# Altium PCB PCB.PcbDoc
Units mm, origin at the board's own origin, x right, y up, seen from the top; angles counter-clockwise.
Board outline 41 x 25.36 mm, 2 copper layers (TOP, BOTTOM), stack 1.586 mm thick; 28 components, 6 nets, 57 pads, 22 vias.
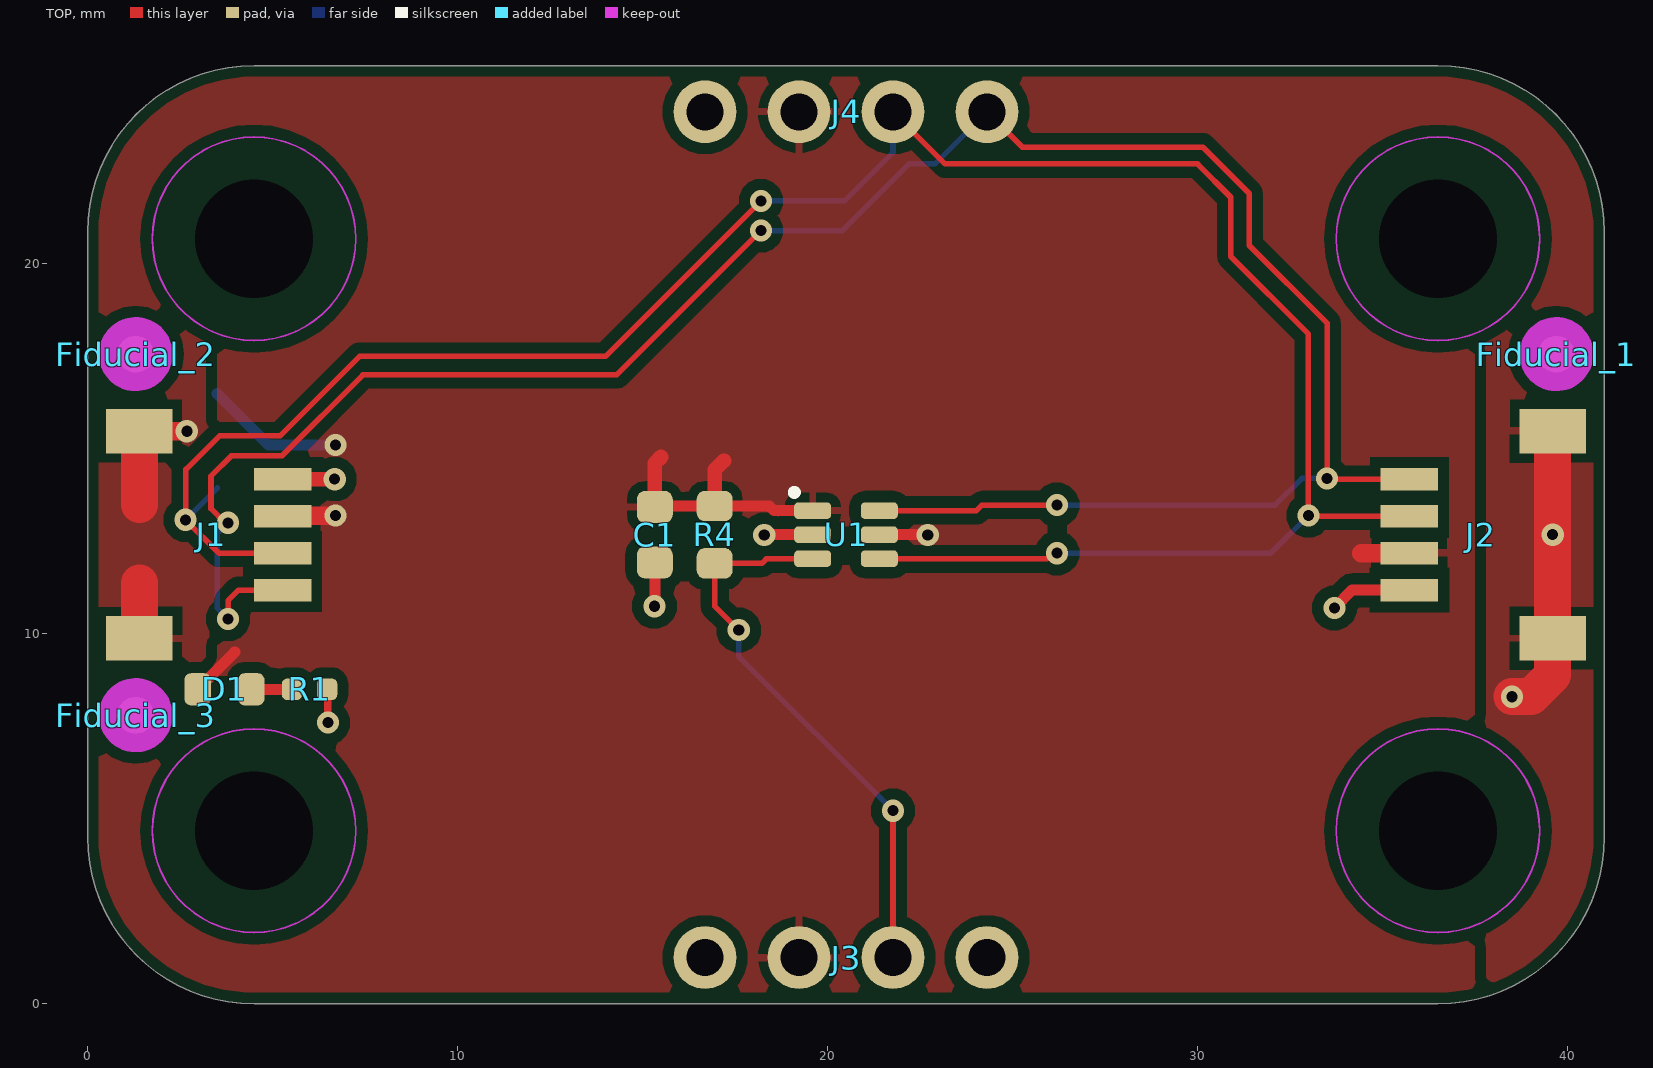
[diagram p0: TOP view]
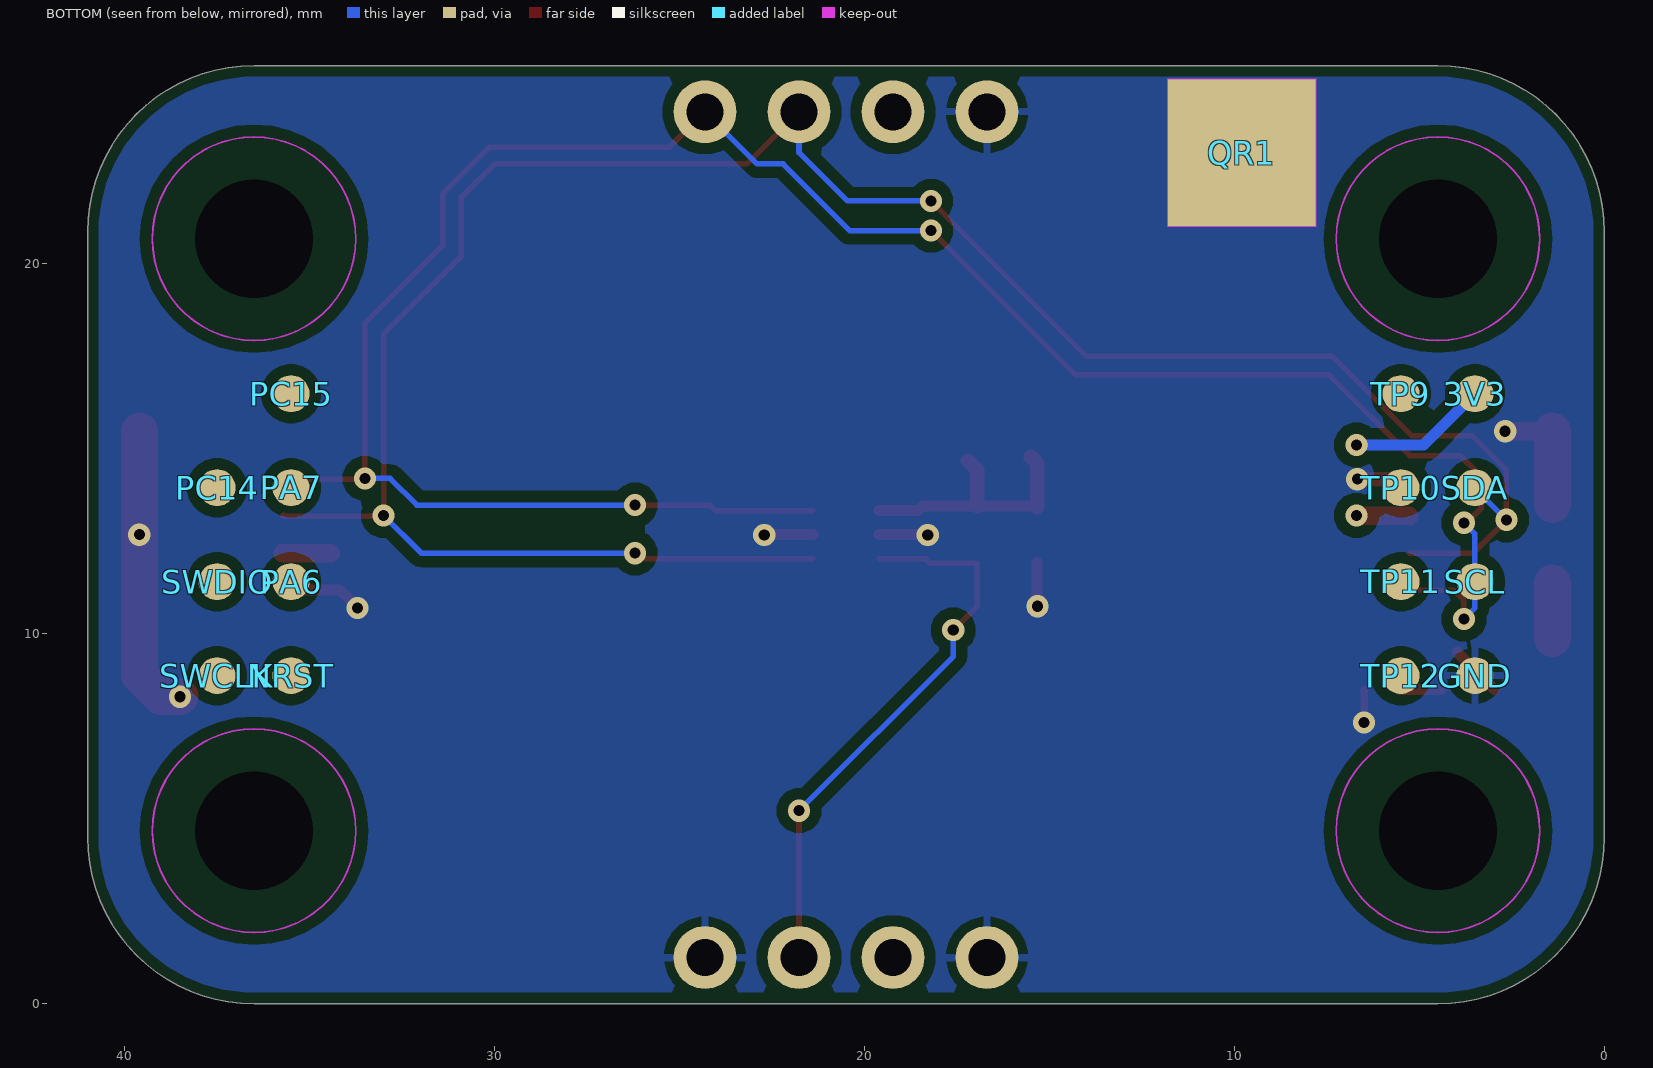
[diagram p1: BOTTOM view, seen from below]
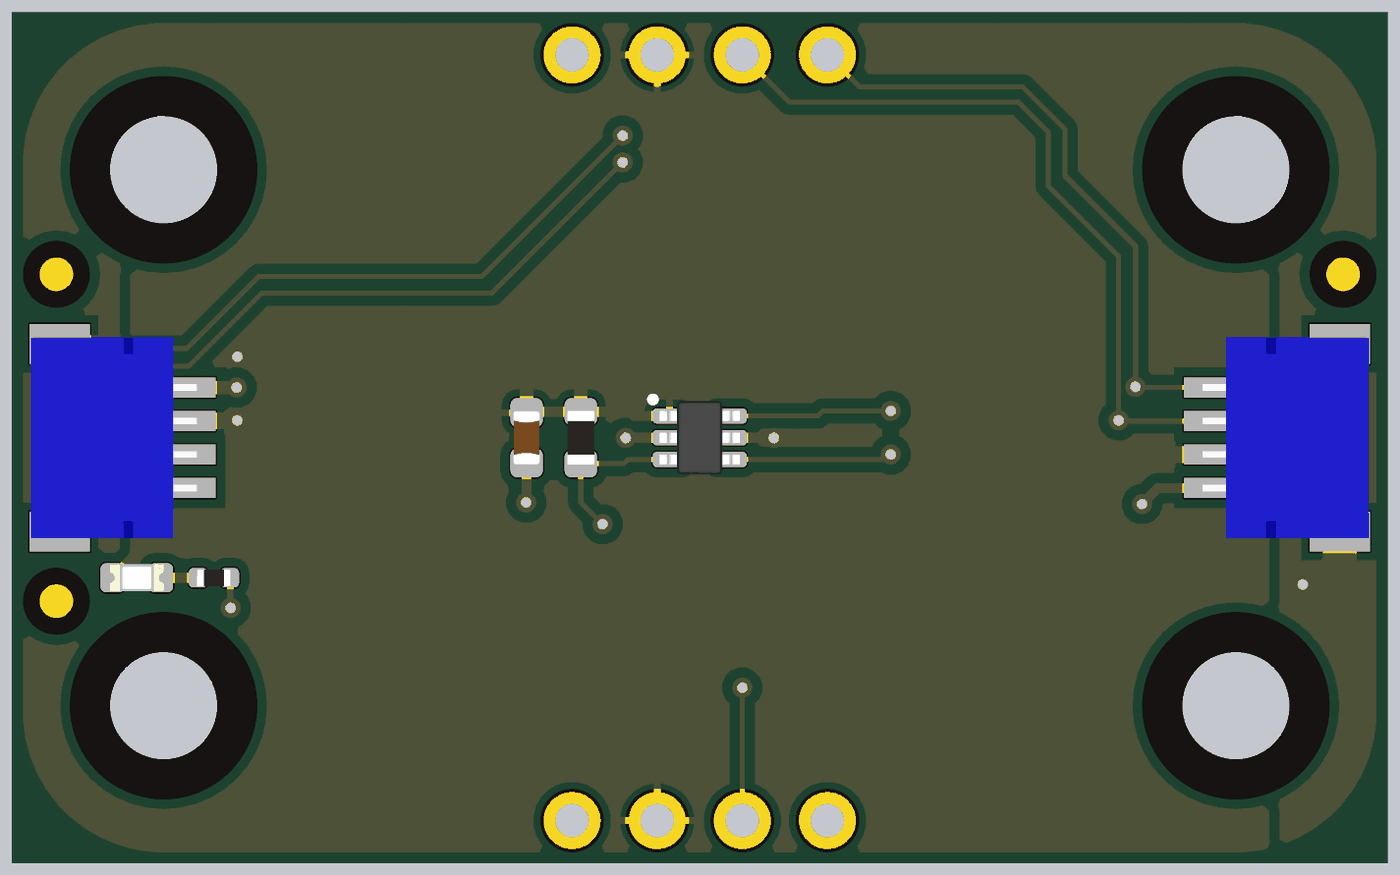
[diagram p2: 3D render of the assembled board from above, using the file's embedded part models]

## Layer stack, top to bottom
Top Solder: solder mask 0.01, Solder Resist, Dk 3.5
TOP: signal copper 0.018
Dielectric: core 1.55, FR-4, Dk 4.8
BOTTOM: signal copper 0.018
Bottom Solder: solder mask 0.01, Solder Resist, Dk 3.5

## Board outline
0,4.5 ccw(c4.5,4.5) 4.5,0 36.5,0 ccw(c36.5,4.5) 41,4.5 41,20.86 ccw(c36.5,20.86) 36.5,25.36 4.5,25.36 ccw(c4.5,20.86) 0,20.86

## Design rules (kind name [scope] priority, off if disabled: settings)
BoardOutlineClearance Mousebites [(ObjectKind = 'Pad') And (Name = 'Free-MOUSEBITE')] p1: gap=0 ignorepadtopadclearanceinfootprint=FALSE
BoardOutlineClearance Silks [(OnLayer('Top Overlay') OR OnLayer('Bottom Overlay'))] p2: gap=0 ignorepadtopadclearanceinfootprint=FALSE
BoardOutlineClearance [All] p3: gap=0.3 ignorepadtopadclearanceinfootprint=FALSE
Clearance COPPER_0.3mm [All] p1: gap=0.127 ignorepadtopadclearanceinfootprint=FALSE except(0.3: Arc-Fill Arc-Poly Arc-Region Track-Fill Track-Poly Track-Region SMDPad-Fill SMDPad-Poly SMDPad-Region THPad-Fill THPad-Poly THPad-Region Via-Fill Via-Poly Via-Region Fill-Fill Fill-Poly Fill-Region Poly-Poly Poly-Region Region-Region)
Clearance "Generic clearance 0.15mm" [All] p2: gap=0.15 ignorepadtopadclearanceinfootprint=FALSE
ComponentClearance [All] p1: gap=0.2 collisioncheckmode=3 verticalgap=0 showdistances=TRUE
DiffPairsRouting USB [InDifferentialPairClass('USB')] p1: maxlimit=0.15 minlimit=0.15 mostfreqgap=0.15 toplayer_minwidth=0.15 toplayer_maxwidth=0.21 toplayer_prefwidth=0.2 bottomlayer_minwidth=0.15 bottomlayer_maxwidth=0.21 bottomlayer_prefwidth=0.2 impedanceprofiledriven=TRUE impedanceprofileid={E6B00C31-4C8E-439C-824F-D2B2CDC26F9C} impedanceprofilevalue=90.000000 maxuncoupledlength=12.7
Height [All] p1: minheight=0 maxheight=30 prefheight=12.7
HoleSize [All] p1: absolutevalues=TRUE maxlimit=30 minlimit=0.3 maxpercent=80.000 minpercent=20.000
HoleToHoleClearance [All] p1: gap=0.25 allowstackedmicrovias=FALSE
MinimumAnnularRing [All] p1: minimumring=0.15
PlaneConnect [All] p1: pad.planeconnectstyle=Relief pad.reliefexpansion=0.508 pad.reliefentries=4 pad.reliefconductorwidth=0.254 pad.reliefairgap=0.254 via.planeconnectstyle=Direct via.reliefexpansion=0.508 via.reliefentries=4 via.reliefconductorwidth=0.254 via.reliefairgap=0.254
PolygonConnect QR_POLYGONCONNECT [(ObjectKind = 'Pad') And (Name = 'QR1-PAD')] p1: connectstyle=Direct reliefconductorwidth=0.254 reliefentries=4 polygonreliefangle="90 Angle" airgapwidth=0.254
PolygonConnect [All] p2: thpad.connectstyle=Relief thpad.reliefconductorwidth=0.2 thpad.reliefentries=4 thpad.polygonreliefangle="90 Angle" thpad.airgapwidth=0.254 smdpad.connectstyle=Relief smdpad.reliefconductorwidth=0.2 smdpad.reliefentries=4 smdpad.polygonreliefangle="90 Angle" smdpad.airgapwidth=0.254 via.connectstyle=Direct via.reliefconductorwidth=0.254 via.reliefentries=4 via.polygonreliefangle="90 Angle" via.airgapwidth=0.254
RoomDefinition TOP [InComponentClass('TOP')] p1: confinementstyle=ConfineIn formatcopy=TRUE lockcomponents=FALSE outline 45,5.2 49.9,5.2 49.9,18.4 45,18.4
RoutingVias StandardVias [All] p1: holewidth=0.3 width=0.6 viastyle="Through Hole" minholewidth=0.3 minwidth=0.6 maxholewidth=0.3 maxwidth=0.6
SMDToCorner [All] p1: distance=39370
SilkToSilkClearance [All] p1: silktosilkclearance=0.2
SilkToSolderMaskClearance [IsPad] p1: minsilkscreentomaskgap=0.15 clearancetoexposedcopper=TRUE
SolderMaskExpansion VIAtented [IsVia] p1: expansion=0.102 istentingtop=TRUE
SolderMaskExpansion [All] p2: expansion=0.05 istentingtop=FALSE
SupplyNets "Schematic Supply Nets_1" [InNet('GND')] p1: voltage=0.000
SupplyNets "Schematic Supply Nets" [InNet('+3V3')] p2: voltage=0.000
UnConnectedPin [All] p1:
UnRoutedNet [NOT WithinRoom('K36')] p1: checkbadconnections=TRUE
ViasUnderSMD [All] p1: allowed=FALSE
Width StandardTraces [All] p1: maxlimit=5 minlimit=0.15 preferedwidth=0.15 minimp=50.000000 maximp=50.000000 favimp=50.000000
21 further rules are at their usual default settings.

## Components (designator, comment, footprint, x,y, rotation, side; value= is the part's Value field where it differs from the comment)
3V3 "Test point 1.00mm" TP-1.00MM 3.5,16.49 r90 bottom
C1 "GRM188R61A106KE69D" CAP-0603 15.333,12.68 r90 top value=10µF
D1 "LTST-C190KGKT" LEDC1608X80N-AK 3.7,8.5 r180 top
Fiducial_1 "Fiducial mark 1mm" "Fiducial mark 1mm-Footprint-1" 39.7,17.56 r270 top
Fiducial_2 "Fiducial mark 1mm" "Fiducial mark 1mm-Footprint-1" 1.3,17.56 r270 top
Fiducial_3 "Fiducial mark 1mm" "Fiducial mark 1mm-Footprint-1" 1.3,7.8 r270 top
GND "Test point 1.00mm" TP-1.00MM 3.5,8.87 r90 bottom
J1 "SM04B-SRSS-TB(LF)(SN)" SM04B-SRSS-TB(LF)(SN)-Footprint-1 3.337,12.68 r90 top locked
J2 "SM04B-SRSS-TB(LF)(SN)" SM04B-SRSS-TB(LF)(SN)-Footprint-1 37.663,12.68 r270 top locked
J3 "HEADER TH 2.54mm VERT. 1x004POS" "PIN HEADER 2.54mm VERT. 1x4POS-Footprint-1" 20.5,1.25 r0 top
J4 "HEADER TH 2.54mm VERT. 1x004POS" "PIN HEADER 2.54mm VERT. 1x4POS-Footprint-1" 20.5,24.11 r0 top
NRST "Test point 1.00mm" TP-1.00MM 35.5,8.87 r180 bottom
PA6 "Test point 1.00mm" TP-1.00MM 35.5,11.41 r180 bottom
PA7 "Test point 1.00mm" TP-1.00MM 35.5,13.95 r180 bottom
PC14 "Test point 1.00mm" TP-1.00MM 37.5,13.95 r180 bottom
PC15 "Test point 1.00mm" TP-1.00MM 35.5,16.49 r180 bottom
QR1 "QR CODE 4x4mm" "QR CODE 4x4mm" 9.8,23 r180 bottom
R1 "CRCW04021K00FKEDC" RES-0402 6,8.5 r180 top value=1k
R4 "RC0603FR-0710KL" RES-0603 16.951,12.68 r90 top value=10k
SCL "Test point 1.00mm" TP-1.00MM 3.5,11.41 r90 bottom
SDA "Test point 1.00mm" TP-1.00MM 3.5,13.95 r90 bottom
SWCLK "Test point 1.00mm" TP-1.00MM 37.5,8.87 r180 bottom
SWDIO "Test point 1.00mm" TP-1.00MM 37.5,11.41 r180 bottom
TP9 "Test point 1.00mm" TP-1.00MM 5.5,16.49 r0 bottom
TP10 "Test point 1.00mm" TP-1.00MM 5.5,13.95 r0 bottom
TP11 "Test point 1.00mm" TP-1.00MM 5.5,11.41 r0 bottom
TP12 "Test point 1.00mm" TP-1.00MM 5.5,8.87 r0 bottom
U1 "LTC4311ISC6#TRMPBF" "SC70 - 6 Leads" 20.5,12.68 r0 top

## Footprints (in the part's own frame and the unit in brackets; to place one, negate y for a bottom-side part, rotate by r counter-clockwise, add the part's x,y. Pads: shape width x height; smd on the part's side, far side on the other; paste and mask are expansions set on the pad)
CAP-0603 [mm] "Chip Capacitor, Body 0603 imperial,1.6x0.8mm, IPC High Density"
  rrect51% 0.87x0.97 smd mask+0.05: 1(-0.75,0) 2(0.75,0)
  body extent -0.8,-0.4 0.8,0.4, height 0.8
"Fiducial mark 1mm-Footprint-1" [mm]
  round 1 smd paste-10 mask+0.5: 1(0,0)
  TOP keep-out circle w1: c0,0 r0.5
LEDC1608X80N-AK [mm]
  rrect50% 0.72x0.87 smd: A(0.725,0) C(-0.725,0)
  body extent -0.8,-0.4 0.8,0.4, height 0.79
"PIN HEADER 2.54mm VERT. 1x4POS-Footprint-1" [mm]
  round 1.7 hole 1 mask+0.1: 1(-3.81,0) 2(-1.27,0) 3(1.27,0) 4(3.81,0)
"QR CODE 4x4mm" [mm]
  rect 4x4 smd paste-2539.97 mask+0.1: PAD(0,0)
  TOP keep-out region: -2,2 2,2 2,-2 -2,-2
RES-0402 [mm] "Chip Resistor, 2-Leads, Body  0402 (in) 1005 (mm), IPC Medium Density"
  rrect51% 0.55x0.58 smd mask+0.05: 1(-0.475,0) 2(0.475,0)
  body extent -0.5,-0.25 0.5,0.25, height 0.34
RES-0603 [mm] "Chip Resistor - Body 0603 imperial,1.6x0.8mm, IPC High Density"
  rrect51% 0.82x0.97 smd mask+0.05: 1(-0.775,0) 2(0.775,0)
  body extent -0.8,-0.4 0.8,0.4, height 0.43
"SC70 - 6 Leads" [mm] "SC70, 6-Leads, Body 2,00x2,00mm, Pitch 0,65mm, IPC Medium Density"
  rrect50% 1x0.45 smd mask+0.05: 1(-0.9,0.65) 2(-0.9,0) 3(-0.9,-0.65) 4(0.9,-0.65) 5(0.9,0) 6(0.9,0.65)
  silkscreen extent -1.45,1.09 -1.35,1.19, body extent -1.2,-1.1 1.2,1.1, height 1
SM04B-SRSS-TB(LF)(SN)-Footprint-1 [mm]
  rect 0.6x1.55 smd mask+0.05: 1(1.5,-1.937) 2(0.5,-1.937) 3(-0.5,-1.937) 4(-1.5,-1.937)
  rect 1.2x1.8 smd mask+0.05: FIX(-2.8,1.938) FIX(2.8,1.938)
  body extent -3,-2.16 3,2.8, height 2.98
TP-1.00MM [mm]
  rrect100% 1x1 smd paste-2.54: X(0,0)

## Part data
3V3 GND NRST PA6 PA7 PC14 PC15 SCL SDA SWCLK SWDIO TP9 TP10 TP11 TP12: library part UT0013-A.6, Manufacturer="This is not a component"
C1: library part C0163-A.1, "CAP CHIP 0603 10uF 10% 10V X5R", Case Code (Imperial)=0603, Dielectric=X5R, Manufacturer=Murata, Tolerance=10%, Voltage=10V
D1: library part L0009-A.6, "LED SMD 0603 GREEN/568 15mcd 120^", Manufacturer=Liteon
Fiducial_1 Fiducial_2 Fiducial_3: library part UT0023-A.7, "Fiducial mark 1mm clearance 2mm"
J1 J2: library part J0005-A.3, "CONN JST SH 1mm 4POS HORIZONTAL TIN QWIIC", LCSC Part #=C160404, Manufacturer=JST
J3 J4: library part J0162-A.6
QR1: library part QR-0001-A.5, "QR CODE 4x4mm on layer 34 (This is not a component)", Manufacturer="This is not a component"
R1: library part R0007-A.24, "RES CHIP 0402 1k 1% 1/16W", Case Code (Imperial)=0402, Manufacturer=Vishay, Power=62.5mW, Temperature Coefficient=100ppm, Tolerance=1%
R4: library part R0292-A.1, "RES CHIP 0603 10k 1% 1/10W", Case Code (Imperial)=0603, Manufacturer=YAGEO, Power=100mW, Temperature Coefficient=100ppm, Tolerance=1%
U1: library part U0468-A.1, "I2C/SMBus Accelerator, VCC 1.6V-5.5V, SC70 2mm x 2mm", Manufacturer="ANALOG DEVICES"

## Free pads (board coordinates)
  round 3 hole 3.2 unplated paste-2539.97 mask+1.3: MH(4.5,4.68) MH(4.5,20.68) MH(36.5,4.68) MH(36.5,20.68)

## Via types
v1: diameter 0.6, hole 0.3, TOP to BOTTOM, tented both sides, 22 vias

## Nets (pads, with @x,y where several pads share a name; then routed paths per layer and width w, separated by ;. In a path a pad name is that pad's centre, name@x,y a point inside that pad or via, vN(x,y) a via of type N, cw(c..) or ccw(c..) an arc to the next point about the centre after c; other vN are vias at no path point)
+3V3: 3V3.X C1.2 D1.A J1.2 J2.2 J3.2 J4.2 R4.2 U1.1 | length 15
  TOP w0.3: D1.A 3.98,9.505 ; C1.2 15.358,13.455 R4.2 18.425,13.455 18.55,13.33 U1.1
  TOP w0.4: C1.2 15.333,14.613 15.5,14.78 ; R4.2 16.951,14.431 17.2,14.68
  TOP w0.5: J1.2 5.284,13.19 6.69,13.19 v1(6.7,13.2) ; 34.42,12.18 J2.2
  BOTTOM w0.3: 3V3.X 4.89,15.1 v1(6.7,15.1)
EN_1: J3.3 R4.1 U1.3 | length 15.4
  TOP w0.15: v1(17.6,10.1) 16.951,10.749 R4.1 18.225,11.905 18.35,12.03 U1.3 ; J3.3 v1(21.77,5.22)
  BOTTOM w0.15: v1(17.6,10.1) 17.6,9.39 v1(21.77,5.22)
GND: C1.1 GND.X J1.1 J1.FIX J2.1 J2.FIX J3.1 J3.4 J4.1 QR1.PAD R1.1 U1.2 U1.5 | length 21.1
  TOP w0.2: R1.1 6.488,8.488 6.488,7.612 v1(6.5,7.6)
  TOP w0.3: v1(15.32,10.746) 15.333,10.758 C1.1 ; v1(18.291,12.675) 18.296,12.68 U1.2 ; U1.5 v1@22.704,12.68 ; v1(33.7,10.7) 34.18,11.18 J2.1 J2.1@35.72,11.185
  TOP w0.4: J1.1 v1(6.68,14.18)
  TOP w0.5: J1.FIX@1.399,15.48 2.678,15.48 v1(2.683,15.475)
  TOP w1: J1.FIX@1.399,9.88 1.399,11.379 ; 1.399,13.499 J1.FIX@1.399,15.48 ; v1(38.5,8.3) 39.015,8.3 39.601,8.886 J2.FIX@39.601,9.88 ; J2.FIX@39.6,9.881 J2.FIX@39.6,15.48
  other v1: 22.709,12.675 39.6,12.68
NetD1_C: D1.C R1.2 | length 1.1
  TOP w0.3: D1.C R1.2
SCL_1: J1.4 J2.4 J4.4 SCL.X U1.6 | length 63
  TOP w0.15: v1(3.8,10.4) 3.8,10.9 4.08,11.18 J1.4 ; v1(3.8,13) 3.723,13 3.337,13.386 3.337,14.262 3.888,14.813 5.257,14.813 7.444,17 14.3,17 v1(18.2,20.9) ; U1.6 24.024,13.33 24.174,13.48 v1(26.2,13.48) ; J4.4 25.263,23.157 30.143,23.157 31.4,21.9 31.4,20.5 33.502,18.398 v1(33.502,14.2) 33.522,14.18 J2.4 J2.4@35.546,14
  BOTTOM w0.15: v1(3.8,10.4) 3.5,10.7 3.5,12.7 v1(3.8,13) ; v1(18.2,20.9) 20.4,20.9 22.2,22.7 22.9,22.7 J4.4 ; v1(26.2,13.48) 32.1,13.48 32.82,14.2 v1(33.502,14.2)
SDA_1: J1.3 J2.3 J4.3 SDA.X U1.4 | length 63.8
  TOP w0.15: 2.65,14.45 v1(2.65,13.082) 3.554,12.178 3.895,12.178 3.897,12.18 J1.3 ; 2.66,14.44 3.569,15.349 5.205,15.349 7.356,17.5 14,17.5 v1(18.2,21.7) ; U1.4 25.928,12.03 26.078,12.18 v1(26.2,12.18) ; J4.3 23.18,22.7 30,22.7 30.9,21.8 30.9,20.2 33,18.1 v1(33,13.2) 33.02,13.18 J2.3 J2.3@35.706,13.2
  BOTTOM w0.15: v1(2.65,13.082) 3.5,13.932 SDA.X ; v1(18.2,21.7) 20.46,21.7 21.77,23.01 J4.3 ; v1(26.2,12.18) 31.98,12.18 v1(33,13.2)
pads on no net: Fiducial_1.1 Fiducial_2.1 Fiducial_3.1 NRST.X PA6.X PA7.X PC14.X PC15.X SWCLK.X SWDIO.X TP9.X TP10.X TP11.X TP12.X

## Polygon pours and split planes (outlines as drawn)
GND on TOP "NONET_L04_P-001" (solid, remove dead copper, pour order 9): 0,4.5 ccw(c4.5,4.5) 4.5,0 36.5,0 ccw(c36.5,4.5) 41,4.5 41,20.86 ccw(c36.5,20.86) 36.5,25.36 4.5,25.36 ccw(c4.5,20.86) 0,20.86
+3V3 on TOP "NONET_L04_P-001" (solid, remove dead copper, pour order 8): 0,4.5 ccw(c4.5,4.5) 4.5,0 36.5,0 ccw(c36.5,4.5) 41,4.5 41,20.86 ccw(c36.5,20.86) 36.5,25.36 4.5,25.36 ccw(c4.5,20.86) 0,20.86
GND on TOP "NONET_L04_P-001" (solid, remove dead copper, pour order 6): 0,25.36 0,0 3.2,0 3.2,25.36
GND on TOP "NONET_L04_P-001" (solid, remove dead copper, pour order 5): 41,25.36 41,0 37.8,0 37.8,25.36
GND on BOTTOM "NONET_L04_P-001" (solid, remove dead copper, pour order 10): 0,4.5 ccw(c4.5,4.5) 4.5,0 36.5,0 ccw(c36.5,4.5) 41,4.5 41,20.86 ccw(c36.5,20.86) 36.5,25.36 4.5,25.36 ccw(c4.5,20.86) 0,20.86

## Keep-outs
Keep-Out Layer:
  circle w0.05: c36.5,4.68 r2.75
  circle w0.05: c36.5,20.68 r2.75
  circle w0.05: c4.5,4.68 r2.75
  circle w0.05: c4.5,20.68 r2.75

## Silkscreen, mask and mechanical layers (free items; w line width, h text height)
Route Tool Path:
  lines w2: -1,8.498 -1,16.86 ; 42,4.5 cw(c36.5,4.5) 36.5,-1 ; 42,8.498 42,16.86 ; -1,4.498 cw(c0,4.5) -1,4.5 ccw(c4.5,4.5) -1,4.498 ; -1,4.498 ccw(c4.5,4.5) 4.498,-1 ; -1,20.86 cw(c4.5,20.86) 4.5,26.36 ; -1,20.86 -1,20.86 ; 4.498,-1 ccw(c4.5,0) 4.5,-1 ; 4.498,-1 ccw(c4.5,4.5) 4.5,-1 ; 4.5,-1 36.5,-1 ; 4.5,26.36 4.5,26.36 ; 4.5,26.36 36.5,26.36 ; 36.5,-1 36.5,-1 ; 36.5,26.36 cw(c36.5,25.36) 36.502,26.36 ; 36.5,26.36 cw(c36.5,20.86) 36.502,26.36 ; 36.502,26.36 cw(c36.5,20.86) 42,20.863 ; 42,20.863 cw(c36.5,20.86) 42,20.86 ccw(c41,20.86) 42,20.863
Board:
  the board outline again, w0.05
